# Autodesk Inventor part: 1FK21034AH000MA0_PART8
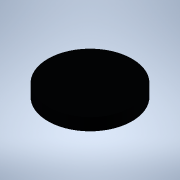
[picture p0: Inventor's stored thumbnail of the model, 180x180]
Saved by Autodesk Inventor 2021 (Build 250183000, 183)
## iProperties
Created: 2025-04
Part Number: 1FK21034AH000MA0_PART8
Material: Generic
Catalog Web Link: www.3dfindit.com
Description: -Servo synchronous motor
Document SubType Name: Modeling
Designer: psAdmin
Mass: 0.299142 g
Surface Area: 3.8585 cm^2
Volume: 0.299142 cm^3
Density: 1 g/cm^3
Appearance: PSOLRGB-38-46-56
Category: PARTsolutions
Title: 1FK21034AH000MA0_PART8
Author: Cadenas PARTsolutions
Comments: Servo synchronous motor
Sending System: PARTsolutions
Preprocessor: ST-DEVELOPER v19.3
PSOL_IDENT_0: {$CADENAS_DATA/23d-libs/siemens_ag/_cat_/ec/b7/1fk21034ah000ma0.prj},213 {VTYP=3D},{NB=1FK21034AH000
PSOL_IDENT_1: MA0_PART8},{LINA=1FK21034AH000MA0_PART8},{NN=1FK21034AH000MA0_PART8},{NOPRJ=TRUE},{DATE=19.08.2025 1
PSOL_IDENT_2: 4:01:05},{GEOMDATE=30.07.2025 02:01:02},{VERSION=},{LINEID=10},{WBVAR=},{WBNUMERIC=}  {NB=1FK21034AH
PSOL_IDENT_3: 000MA0_PART8},{LINA=1FK21034AH000MA0_PART8},{KT=DUMMY},{PREVIEW=../../../_pool_/7c/50/p_d211_xx_0093
PSOL_IDENT_4: 2j.png},{DESCSHORT=SIMOTICS S-1FK2 HD, SINAMICS S210 3AC 400V-480V, 1.01 Nm, 4500 rpm},{DESCLONG=SIM
PSOL_IDENT_5: OTICS S-1FK2 HD servo motor M0=1.27 Nm; PN = 0.48 kW at nN=4500 rpm (380-480 V); PN = 0.3 kW at nN=2
PSOL_IDENT_6: 500 rpm (200-240 V); degree of protection IP64; cylindrical shaft D14 x 30 mm; absolute encoder 22-b
PSOL_IDENT_7: it + 12-bit multiturn (encoder AM22DQC); with OCC interface; plug size M17, rotatable; SIMOTICS S-1F
PSOL_IDENT_8: K2 servomotorfor a wide range of uses in industrial environments. SIMOTICS S‑1FK2 servomotors are co
PSOL_IDENT_9: mpact synchronous motors with a high dynamic performance that set themselves apart as a result of th
PSOL_IDENT_10: eir high power density, degree of protection and overload capability. The motors are available in tw
PSOL_IDENT_11: o variants: as High Dynamic variant (highest dynamic performance as a result of the low intrinsic mo
PSOL_IDENT_12: ment of inertia for applications demanding a high dynamic performance with low moved masses) - and a
PSOL_IDENT_13: s Compact variant (precise and stable closed-loop control for medium up to large moved masses as a r
PSOL_IDENT_14: esult of a medium intrinsic moment of inertia). SIMOTICSS‑1FK2 servomotors fully exploit their stren
PSOL_IDENT_15: gths in a system with the SINAMICSS210 frequency converter and simple connection using the one cable
PSOL_IDENT_16: connection (OCC). Advantages include the short control and positioning times, fast and precise corr
PSOL_IDENT_17: ection of disturbing quantities as well as stable control with a high dynamic performance. The servo
PSOL_IDENT_18: motors can be configured to address a wide range of requirements. For example with and without hold
PSOL_IDENT_19: ing brake, IP64 or IP65 degree of protection, singleturn or multiturn absolute encoders - to name ju
PSOL_IDENT_20: st a few. Further, the servomotors are available in different shaft heights extending from 20 to 100
PSOL_IDENT_21: . A shaft sealing ring is available to achieve an IP65 degree of protection and for subsequent mount
PSOL_IDENT_22: ing at the motor or as spare part. SIMOTICS - the optimum motor for each and every motion control ap
PSOL_IDENT_23: plication.},{INTNO=4034106444822},{SUPPLIERALTNO=1FK2103-4AH00-0MA0},{MANUID=1FK21034AH000MA0},{MANU
PSOL_IDENT_24: NAME=Siemens},{MANUTYPEDESC=SYNCHRONOUS MOTOR 1FK2 HD 1,27 NM},{AAU732=SIMOTICS},{AAO057=S-1FK2},{AA
PSOL_IDENT_25: U734=SIMOTICS S-1FK2 HD servo motor M0=1.27 Nm; PN = 0.48 kW at nN=4500 rpm (380-480 V); PN = 0.3 kW
PSOL_IDENT_26: at nN=2500 rpm (200-240 V); degree of protection IP64; cylindrical shaft D14 x 30 mm; absolute enco
PSOL_IDENT_27: der 22-bit + 12-bit multiturn (encoder AM22DQC); with OCC interface; plug size M17, rotatable;},{AAW
PSOL_IDENT_28: 338=SYNCHRONOUS MOTOR 1FK2 HD 1,27 NM},{AAO742=SIMOTICS},{AAO663=4034106444822},{NOCUPEROU=1},{PRICE
PSOL_IDENT_29: QUANTITY=1},{QUANTITYMIN=1},{QUANTITYINT=1},{CTN=85015100},{COO=RO},{AAO676=1FK2103-4AH00-0MA0},{AAO
PSOL_IDENT_30: 677=Siemens AG},{ORDERUNIT=C62},{CONTENTUNIT=C62}
NB: 1FK21034AH000MA0_PART8
NT: Servo synchronous motor
NBSYN: $MANUID._PART8
LINA: 1FK21034AH000MA0_PART8
CATALOG: SIEMENS
PREVIEW: ../../../_pool_/7c/50/p_d211_xx_00932j.png
DESCSHORT: SIMOTICS S-1FK2 HD, SINAMICS S210 3AC 400V-480V, 1.01 Nm, 4500 rpm
DESCLONG: SIMOTICS S-1FK2 HD servo motor M0=1.27 Nm; PN = 0.48 kW at nN=4500 rpm (380-480 V); PN = 0.3 kW at nN=2500 rpm (200-240 V); degree of protection IP64; cylindric
INTNO: 4034106444822
SUPPLIERALTNO: 1FK2103-4AH00-0MA0
MANUID: 1FK21034AH000MA0
MANUNAME: Siemens
MANUTYPEDESC: SYNCHRONOUS MOTOR 1FK2 HD 1,27 NM
AAU732: SIMOTICS
AAO057: S-1FK2
AAU734: SIMOTICS S-1FK2 HD servo motor M0=1.27 Nm; PN = 0.48 kW at nN=4500 rpm (380-480 V); PN = 0.3 kW at nN=2500 rpm (200-240 V); degree of protection IP64; cylindric
AAW338: SYNCHRONOUS MOTOR 1FK2 HD 1,27 NM
AAO742: SIMOTICS
AAO663: 4034106444822.0
NOCUPEROU: 1
PRICEQUANTITY: 1
QUANTITYMIN: 1
QUANTITYINT: 1
CTN: 85015100
COO: RO
ARTICLENO: 1FK21034AH000MA0_PART8
BOMINFO: 1FK21034AH000MA0_PART8
CREATOR: CADENAS GmbH
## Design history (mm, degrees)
feature "2025_04_17_15_01_37_0283"
body "Solid1"
